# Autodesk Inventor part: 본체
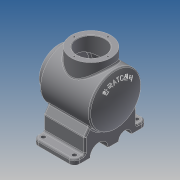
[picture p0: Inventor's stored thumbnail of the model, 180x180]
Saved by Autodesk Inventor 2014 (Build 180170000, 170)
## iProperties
Created: 2018-08
Part Number: 본체
Material: Generic
Document SubType Name: Modeling
Designer: kb542
Density: 1 g/cm^3
Appearance: Default
Author: kb542
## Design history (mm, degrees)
sketch "스케치1"
  geometry: L1 (-60, 27)-(-60, 38); L2 (-60, 38)-(-48, 38); L3 (-48, 38)-(-48, 50); L4 (-48, 50)-(48.671, 50); L5 (-38, 40)-(-38, 27); L6 (-38, 27)-(-60, 27); L7 (60, 0)-(-60, 0); L8 (42.163, 40)-(-38, 40); A1 r 116 centre (-56, 0) between (60, 0) and (48.671, 50); A2 r 106 centre (-56, 0) between (50, 0) and (42.163, 40); 2 further points
  constraints: 16 end point, 4 parallel, 4 point on circle, 2 centre point, 2 coincident, 2 perpendicular, 2 point on line, 1 horizontal alignment, 1 midpoint, 1 vertical, 1 vertical alignment
  dimensions: "d2" = 10 radial gap between concentric circles of A1 A2; "d3" = 116 radius of A1; "d4" = 120 distance from line of L7.start L1; "d5" = 12 distance of L1.end L2.end; "d6" = 100 diameter of L4 L7; "d7" = 76 diameter of L2 L7; "d8" = 54 diameter of L6 L7; "d9" = 22 distance of L5.end L1.start; "d10" = 80 diameter of L8 L7
revolve "회전1" sketch "스케치1" stored, may be unused: angle "d12" = 90 deg
node "작업 평면1"
sketch "스케치2"
  geometry: L1 (48, 50)-(48, -50) reference; C1 r 38 at (-2, 0); 2 further points
  constraints: 1 centre point, 1 coincident, 1 horizontal alignment, 1 midpoint
  dimensions: "d14" = 76 diameter of C1; "d75" = 50 distance from line of point (-2, 0) L1
extrude "돌출1" join sketch "스케치2" stored distance "d15" = 10; taper "d16" = 0 deg
sketch "스케치3"
  geometry: C1 r 38 at (0, 0) reference; C2 r 27 at (0, 0)
  constraints: 1 centre point, 1 coincident
  dimensions: "d17" = 54 diameter of C2
extrude "돌출2" cut sketch "스케치3" stored distance "d18" = 10; taper "d19" = 0 deg
sketch "스케치4"
  geometry: C1 r 27 at (0, 0) reference; 1 further point
  constraints: 1 vertical alignment
  dimensions: "d20" = 32.5 distance of C1.centre point (0, -32.5)
hole "구멍1" sketch "스케치4" at (0, -32.5) diameter "d21" = 3.242; stored, may be unused: countersink angle "d25" = 90 deg, drill point angle "d27" = 118 deg; dims "d22" = 8, "d23" = 4, "d24" = 2, "d26" = 10
sketch "스케치5"
  geometry: L1 (-40.304, -29.59)-(-50, -43.437); L2 (-50, -43.437)-(-50, -72); L3 (-50, -72)-(-70, -72); L4 (-70, -72)-(-70, -82); L5 (70, -82)-(70, -72); L6 (70, -72)-(50, -72); L7 (50, -72)-(50, -43.437); L8 (50, -43.437)-(40.304, -29.59); L9 (-70, -82)-(-40, -82); L10 (-15, -82)-(5, -82); L11 (40, -82)-(70, -82); L12 (-70, -72)-(-40.304, -29.59); L13 (40.304, -29.59)-(70, -72); A1 r 50 centre (0, 0) between (-40.304, -29.59) and (40.304, -29.59) reference; A2 r 12.5 centre (-27.5, -82) between (-15, -82) and (-40, -82); A3 r 17.5 centre (22.5, -82) between (40, -82) and (5, -82); 1 further point
  constraints: 26 end point, 10 perpendicular, 6 point on circle, 4 equal length, 3 horizontal alignment, 2 centre point, 1 collinear, 1 vertical
  dimensions: "d31" = 20 distance between parallel lines of L4 L2; "d32" = 35 deg angle of L5 L8; "d33" = 35 deg angle of L4 L1; "d36" = 25 diameter of A2; "d37" = 35 diameter of A3; "d40" = 10 distance between parallel lines of L11 L6; "d41" = 27.5 horizontal distance of point (0, 0) A2.centre; "d42" = 22.5 horizontal distance of point (0, 0) A3.centre; "d43" = 140 distance between parallel lines of L4 L5; "d44" = 70 distance from line of L4 point (0, 0); "d45" = 82 distance from line of A1.centre L11
extrude "돌출3" join sketch "스케치5" stored distance "d46" = 80; taper "d47" = 0 deg
sketch "스케치6"
  geometry: C1 r 38 at (0, 0) reference; 1 further point
  constraints: 1 horizontal alignment
  dimensions: "d48" = 32.5 distance of C1.centre point (-32.5, 0)
hole "구멍2" sketch "스케치6" at (-32.5, 0) diameter "d49" = 3.242; stored, may be unused: countersink angle "d53" = 90 deg, drill point angle "d55" = 118 deg; dims "d50" = 8, "d51" = 4, "d52" = 2, "d54" = 10
fillet "모깎기1" dims "d59" = 10
sketch "스케치7"
  geometry: L1 (80, -100)-(80, -110) reference; L2 (0, -100)-(80, -100) reference; L3 (0, -110)-(0, -100) reference; L4 (10, -120)-(70, -120) reference; A1 r 10 centre (10, 10) between (10, 20) and (0, 10) reference; A2 r 10 centre (70, 10) between (80, 10) and (70, 20) reference; A3 r 10 centre (70, -110) between (70, -120) and (80, -110) reference; A4 r 10 centre (10, -110) between (0, -110) and (10, -120) reference; 1 further point
hole "구멍3" sketch "스케치7" at (10, 10), (70, 10), (70, -110), (10, -110) diameter "d60" = 8; stored, may be unused: countersink angle "d64" = 90 deg, drill point angle "d66" = 118 deg; dims "d61" = 8, "d62" = 4, "d63" = 2, "d65" = 10
fillet "모깎기2" dims "d67" = 3
chamfer "모따기1" distance "d68" = 1; stored, may be unused: second distance "d69" = 2, angle "d70" = 45 deg
node "작업 평면2"
sketch "스케치8"
  geometry: C1 r 32.5 at (0, 0); 1 further point
  constraints: 1 centre point, 1 coincident, 1 other
  dimensions: "d72" = 65 diameter of C1
feature "엠보싱1" sketch "스케치8" dims "d73" = 0.5, "d74" = 0
node "솔리드1"
pattern_circular "원형 패턴1" dims angle "d29" = 360 deg
pattern_circular "원형 패턴2" dims angle "d57" = 360 deg
node "투영된 루프1"
other parameters: "d13" = 65, "d34" = 82, "d71" = -82.75
